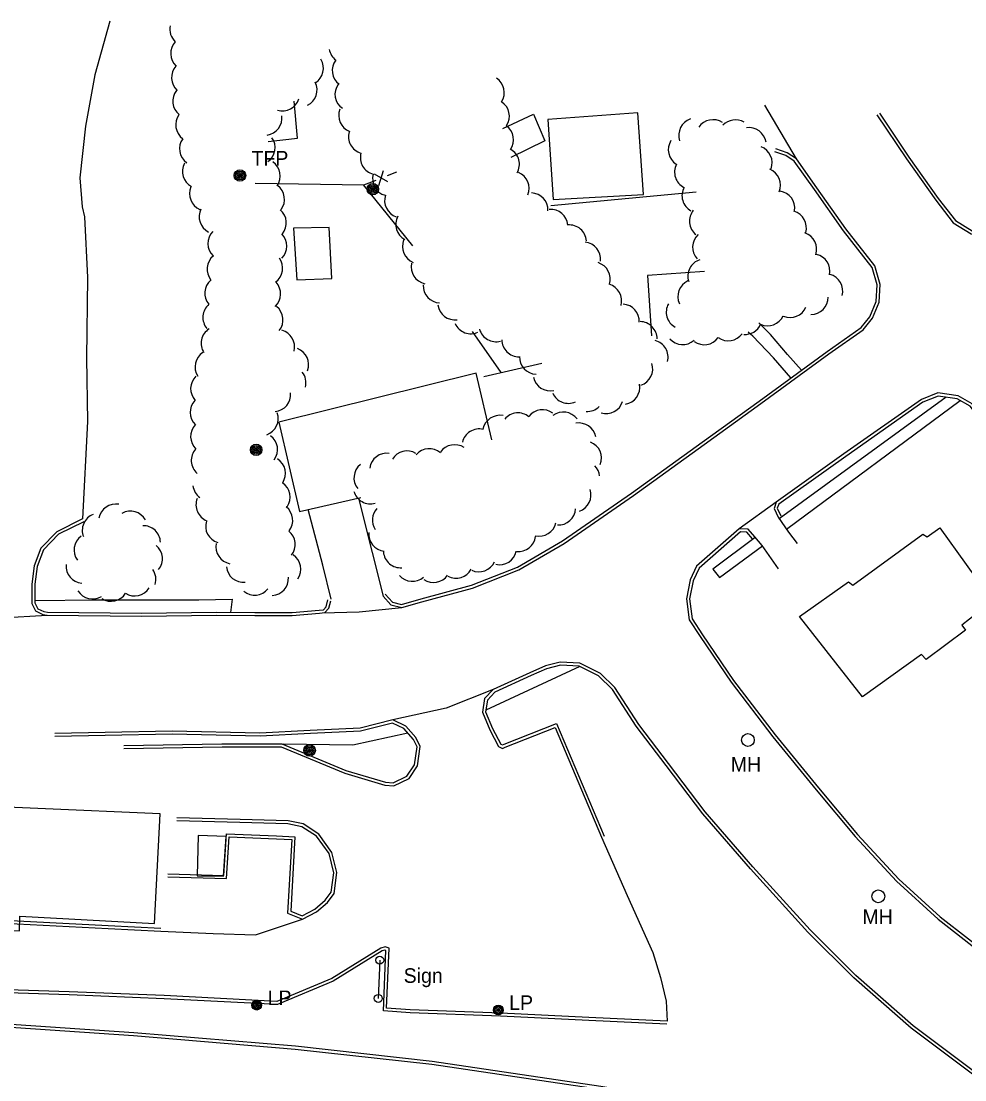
# Model space of a CAD drawing. Extents: x 2402803 to 2427059, y 6985292 to 6997652.
# Drawn here: x 2404260.6 to 2404570.8, y 6991972.5 to 6992320.4 of the extents above; entities that cross this region are included whole.
import ezdxf

# ---------------------------------------------------------------- set-up
doc = ezdxf.new("R2010")
doc.units = 0
for name, color, linetype in [('p_dtm sidewalk', 7, 'Continuous'), ('p_road - paved curb', 7, 'Continuous'), ('p_structure building', 7, 'Continuous'), ('p_structure fence', 7, 'Continuous'), ('p_structure sign', 7, 'Continuous'), ('p_utility manhole', 7, 'Continuous'), ('p_veg woods', 7, 'Continuous')]:
    doc.layers.add(name, color=color, linetype=linetype)

msp = doc.modelspace()

# ---------------------------------------------------------------- linework, layer by layer
at = {"layer": 'p_dtm sidewalk'}
for points in [[(2404517.12, 6992205.74), (2404512.51, 6992210.92), (2404506.95, 6992217.45), (2404503.04, 6992221.25)], [(2404513.62, 6992203.19), (2404507.88, 6992209.81), (2404501.12, 6992216.86), (2404499.61, 6992218.21)], [(2404564.65, 6992196.8), (2404509.76, 6992156.87)], [(2404512.15, 6992153.41), (2404569.21, 6992195.72)], [(2404501.85, 6992150.76), (2404487.91, 6992140.26), (2404490.19, 6992137.57), (2404504.25, 6992148.02)], [(2404265.16, 6992130.01), (2404284.98, 6992130.2), (2404319.04, 6992130.25), (2404329.96, 6992130.47), (2404329.39, 6992126.11)], [(2404444.25, 6992108.33), (2404413.37, 6992093.98)], [(2404387.76, 6992086.41), (2404369.65, 6992082.48), (2404346.71, 6992082.73)]]:
    msp.add_lwpolyline(points, dxfattribs=at)
at = {"layer": 'p_road - paved curb'}
for points in [[(2404289.78, 6992320.43), (2404284.83, 6992302.81), (2404281.76, 6992285.94), (2404279.93, 6992268.95), (2404280.67, 6992259.44), (2404281.41, 6992256.17), (2404282.47, 6992236.2), (2404282.13, 6992209.71), (2404282.44, 6992188.88), (2404280.76, 6992156.81)], [(2404515.43, 6992275.19), (2404505.09, 6992292.79)], [(2404541.89, 6992289.6), (2404551.55, 6992275.14), (2404561.19, 6992261.59), (2404566.97, 6992254.18), (2404572.84, 6992250.5), (2404578.63, 6992250.18), (2404584.37, 6992253.74), (2404606.98, 6992269.73), (2404617.83, 6992277.89)], [(2404542.72, 6992290.16), (2404552.37, 6992275.71), (2404561.99, 6992262.19), (2404567.65, 6992254.93), (2404573.15, 6992251.48), (2404578.37, 6992251.2), (2404583.82, 6992254.57), (2404606.39, 6992270.54), (2404617.23, 6992278.69)], [(2404379.56, 6992131.46), (2404382.08, 6992128.59), (2404385.69, 6992127.7), (2404392.32, 6992129.56), (2404408.92, 6992134.09), (2404424.16, 6992140.05), (2404439.09, 6992148.77), (2404461.82, 6992164.48), (2404485.07, 6992181.25), (2404503.75, 6992194.74), (2404526.08, 6992211.05), (2404537.39, 6992218.98), (2404540.43, 6992222.76), (2404542.62, 6992228.11), (2404542.97, 6992233.92), (2404541.16, 6992239.98), (2404531.68, 6992252.15), (2404522.16, 6992265.68), (2404515.43, 6992275.19), (2404512.36, 6992277.13), (2404508.62, 6992278.47)], [(2404380.31, 6992132.12), (2404382.62, 6992129.49), (2404385.67, 6992128.73), (2404392.05, 6992130.52), (2404408.61, 6992135.04), (2404423.72, 6992140.95), (2404438.55, 6992149.61), (2404461.24, 6992165.3), (2404484.48, 6992182.06), (2404503.16, 6992195.55), (2404525.5, 6992211.86), (2404536.7, 6992219.72), (2404539.56, 6992223.27), (2404541.63, 6992228.34), (2404541.96, 6992233.8), (2404540.26, 6992239.51), (2404530.88, 6992251.55), (2404521.34, 6992265.1), (2404514.73, 6992274.45), (2404511.92, 6992276.23), (2404508.28, 6992277.53)], [(2404652.26, 6992097.97), (2404652.95, 6992100.23), (2404651.9, 6992102.87), (2404645.97, 6992107.33), (2404634.67, 6992118.26), (2404622.7, 6992130.84), (2404611.38, 6992143.67), (2404600.52, 6992157.75), (2404592.54, 6992168.48), (2404582.61, 6992182.29), (2404573.2, 6992194.65), (2404568.54, 6992197.23), (2404561.85, 6992198.22), (2404556.52, 6992196.03), (2404531.05, 6992178.19), (2404508.81, 6992162.33), (2404508.06, 6992160.26), (2404509.4, 6992157.39)], [(2404651.3, 6992098.26), (2404651.89, 6992100.19), (2404651.07, 6992102.24), (2404645.32, 6992106.57), (2404633.96, 6992117.56), (2404621.96, 6992130.16), (2404610.61, 6992143.03), (2404599.72, 6992157.15), (2404591.73, 6992167.89), (2404581.81, 6992181.7), (2404572.53, 6992193.88), (2404568.21, 6992196.27), (2404561.98, 6992197.19), (2404557, 6992195.15), (2404531.63, 6992177.37), (2404509.64, 6992161.7), (2404509.14, 6992160.31), (2404510.31, 6992157.81)], [(2404371.52, 6992163.68), (2404375.95, 6992145.8), (2404379.56, 6992131.46)], [(2404508.81, 6992162.33), (2404496.64, 6992153.58)], [(2404362.48, 6992130.43), (2404359.77, 6992141.59), (2404354.94, 6992159.97)], [(2404509.4, 6992157.39), (2404512.76, 6992152.52), (2404515.68, 6992148.72)], [(2404280.76, 6992156.81), (2404272.31, 6992152.61), (2404267.1, 6992147.18), (2404264.91, 6992141.41), (2404264.12, 6992135.39), (2404264.17, 6992129), (2404265.4, 6992126.57), (2404267.72, 6992125.43), (2404269.17, 6992125.15), (2404300.21, 6992124.81), (2404324.88, 6992125.14), (2404337.39, 6992125.06), (2404349.71, 6992125.06), (2404358.69, 6992125.79), (2404360.45, 6992126.04), (2404361.75, 6992127.47), (2404362.43, 6992129.93)], [(2404281.21, 6992155.91), (2404272.91, 6992151.79), (2404267.96, 6992146.63), (2404265.89, 6992141.16), (2404265.12, 6992135.33), (2404265.17, 6992129.24), (2404266.14, 6992127.32), (2404268.04, 6992126.39), (2404269.27, 6992126.15), (2404300.21, 6992125.81), (2404324.88, 6992126.14), (2404337.39, 6992126.06), (2404349.67, 6992126.06), (2404358.58, 6992126.78), (2404359.95, 6992126.98), (2404360.85, 6992127.97), (2404361.47, 6992130.2)], [(2404501.7, 6992150.93), (2404499.58, 6992153.4), (2404496.64, 6992153.58), (2404482.62, 6992141.29), (2404480.49, 6992136.82), (2404479.25, 6992130.53), (2404480.15, 6992123.66), (2404483.73, 6992118.14), (2404493.97, 6992103.13), (2404507.64, 6992085.19), (2404521.88, 6992067.76), (2404534.69, 6992052.46), (2404548.35, 6992037.72), (2404562.03, 6992025.28), (2404580.65, 6992010.71), (2404597.3, 6991998.61), (2404617.12, 6991985.31), (2404648.64, 6991969.01), (2404673.8, 6991958.27), (2404698.14, 6991949.12), (2404726.05, 6991941.52), (2404750.43, 6991937.37), (2404771.59, 6991934.51), (2404778.59, 6991933.99)], [(2404500.94, 6992150.28), (2404499.1, 6992152.43), (2404496.99, 6992152.56), (2404483.43, 6992140.67), (2404481.45, 6992136.5), (2404480.26, 6992130.5), (2404481.11, 6992124.01), (2404484.56, 6992118.69), (2404494.78, 6992103.72), (2404508.43, 6992085.81), (2404522.65, 6992068.4), (2404535.44, 6992053.12), (2404549.05, 6992038.43), (2404562.68, 6992026.04), (2404581.25, 6992011.51), (2404597.87, 6991999.43), (2404617.63, 6991986.17), (2404649.07, 6991969.92), (2404674.17, 6991959.2), (2404698.45, 6991950.07), (2404726.27, 6991942.5), (2404750.58, 6991938.36), (2404771.69, 6991935.51), (2404778.66, 6991934.99)], [(2404509.56, 6992140.44), (2404504.18, 6992148.12), (2404501.7, 6992150.93)], [(2404359.57, 6992125.91), (2404371.77, 6992126.24), (2404385.69, 6992127.7)], [(2404129.3, 6992124.44), (2404174.84, 6992124.84), (2404202.49, 6992124.13), (2404239.93, 6992124.73), (2404253.96, 6992124.34), (2404269.17, 6992125.15)], [(2404573.9, 6991975.13), (2404553.78, 6991990.21), (2404534.96, 6992006.76), (2404519.93, 6992021.72), (2404501.11, 6992042.43), (2404485.4, 6992060.56), (2404473.36, 6992076.39), (2404463.6, 6992089.27), (2404455.76, 6992101.36), (2404450.99, 6992106.05), (2404444.27, 6992109.44), (2404437.75, 6992109.7), (2404433, 6992108.53), (2404427.82, 6992106.25), (2404415.72, 6992100.71), (2404412.91, 6992097.75), (2404412.26, 6992093.3), (2404414.68, 6992087.46), (2404417.53, 6992082.05), (2404418.77, 6992081.4), (2404419.74, 6992081.83), (2404436.08, 6992088.24), (2404451.31, 6992052.16)], [(2404573.33, 6991974.31), (2404553.15, 6991989.43), (2404534.28, 6992006.03), (2404519.21, 6992021.03), (2404500.36, 6992041.77), (2404484.62, 6992059.93), (2404472.56, 6992075.79), (2404462.78, 6992088.7), (2404454.98, 6992100.72), (2404450.4, 6992105.23), (2404444.01, 6992108.45), (2404437.85, 6992108.7), (2404433.32, 6992107.58), (2404428.23, 6992105.34), (2404416.31, 6992099.88), (2404413.85, 6992097.29), (2404413.29, 6992093.43), (2404415.59, 6992087.89), (2404418.27, 6992082.79), (2404418.81, 6992082.51), (2404419.35, 6992082.75), (2404436.62, 6992089.53), (2404452.23, 6992052.55)], [(2404415.72, 6992100.71), (2404400.36, 6992094.6), (2404382.75, 6992090.74)], [(2404294.35, 6992081.39), (2404326.64, 6992081.87), (2404346.11, 6992081.9), (2404366.97, 6992073.22), (2404380.14, 6992069.31), (2404383.14, 6992069.07), (2404388.11, 6992071.53), (2404390.84, 6992075.62), (2404391.81, 6992082.04), (2404390.39, 6992084.92), (2404387.05, 6992088.73), (2404382.75, 6992090.74), (2404372.02, 6992088.05), (2404355.63, 6992087.31), (2404339.11, 6992086.41), (2404310.23, 6992087.02), (2404288.24, 6992086.65), (2404271.66, 6992086.28)], [(2404294.34, 6992082.39), (2404326.63, 6992082.87), (2404346.31, 6992082.9), (2404367.31, 6992074.16), (2404380.32, 6992070.3), (2404382.94, 6992070.09), (2404387.43, 6992072.31), (2404389.88, 6992075.99), (2404390.77, 6992081.88), (2404389.55, 6992084.36), (2404386.44, 6992087.91), (2404382.65, 6992089.68), (2404372.17, 6992087.06), (2404355.68, 6992086.31), (2404339.13, 6992085.41), (2404310.23, 6992086.02), (2404288.26, 6992085.65), (2404271.68, 6992085.28)], [(2404308.79, 6992039.21), (2404328.13, 6992038.6), (2404329.04, 6992052.3), (2404344.55, 6992051.7), (2404349.54, 6992051.42), (2404348.17, 6992027.26), (2404353.05, 6992025.3), (2404357.68, 6992027.68), (2404361.3, 6992030.79), (2404363.51, 6992033.72), (2404364.43, 6992040.56), (2404362.77, 6992047.22), (2404358.41, 6992053.23), (2404353.29, 6992056.55), (2404348.39, 6992057.59), (2404332.57, 6992058.06), (2404311.78, 6992058.62)], [(2404308.82, 6992040.21), (2404327.2, 6992039.63), (2404328.11, 6992053.34), (2404344.6, 6992052.7), (2404350.6, 6992052.36), (2404349.21, 6992027.92), (2404353, 6992026.4), (2404357.12, 6992028.52), (2404360.57, 6992031.48), (2404362.55, 6992034.11), (2404363.41, 6992040.5), (2404361.85, 6992046.79), (2404357.71, 6992052.49), (2404352.9, 6992055.61), (2404348.27, 6992056.59), (2404332.54, 6992057.06), (2404311.75, 6992057.62)], [(2404451.31, 6992052.16), (2404459.82, 6992033.07), (2404468.18, 6992014.28), (2404470.74, 6992006.13), (2404472.57, 6991998.34), (2404472.91, 6991991.72)], [(2404212.23, 6992047.6), (2404211.55, 6992031.3), (2404216.85, 6992026.5), (2404250.68, 6992024.17), (2404289.19, 6992022.23), (2404306.54, 6992021.29)], [(2404213.23, 6992047.56), (2404212.57, 6992031.73), (2404217.26, 6992027.47), (2404250.74, 6992025.17), (2404289.24, 6992023.23), (2404306.59, 6992022.29)], [(2404306.54, 6992021.29), (2404323.79, 6992020.59), (2404337.68, 6992020.14), (2404353.05, 6992025.3)], [(2404472.86, 6991990.72), (2404447.15, 6991991.98), (2404418.19, 6991993.37), (2404388.47, 6991994.43), (2404379.71, 6991995.13), (2404380.5, 6992015), (2404380.19, 6992015.1), (2404379.23, 6992014.82), (2404363.21, 6992004.87), (2404344.88, 6991997.24), (2404307.61, 6991999.12), (2404276.37, 6992000.36), (2404239.49, 6992001.61)], [(2404472.91, 6991991.72), (2404447.2, 6991992.98), (2404418.23, 6991994.37), (2404388.53, 6991995.43), (2404380.75, 6991996.05), (2404381.53, 6992015.71), (2404380.21, 6992016.15), (2404378.82, 6992015.74), (2404362.75, 6992005.76), (2404344.7, 6991998.25), (2404307.66, 6992000.12), (2404276.41, 6992001.36), (2404239.53, 6992002.61)], [(2404103.33, 6992011.09), (2404106.26, 6992006.83), (2404111.58, 6992001.78), (2404118.26, 6991998.08), (2404128.47, 6991995.82), (2404130.59, 6991995.17), (2404189.8, 6991993.23), (2404247.5, 6991990.45), (2404297.53, 6991986.98), (2404350.67, 6991982.58), (2404395.62, 6991977.57), (2404450.97, 6991969.36), (2404479.18, 6991964.76), (2404478.76, 6991964.34)], [(2404104.15, 6992011.66), (2404107.02, 6992007.48), (2404112.18, 6992002.59), (2404118.62, 6991999.03), (2404128.73, 6991996.79), (2404130.76, 6991996.17), (2404189.84, 6991994.23), (2404247.56, 6991991.45), (2404297.61, 6991987.98), (2404350.77, 6991983.58), (2404395.75, 6991978.56), (2404451.12, 6991970.35), (2404479.79, 6991965.67)]]:
    msp.add_lwpolyline(points, dxfattribs=at)
at = {"layer": 'p_structure building'}
for points in [[(2404341.86, 6992280.9), (2404351.45, 6992281.92), (2404350.35, 6992294.19)], [(2404418.95, 6992285.19), (2404429.05, 6992289.85), (2404432.75, 6992281.07), (2404421.58, 6992275.67)], [(2404434.69, 6992259.86), (2404482.42, 6992264.3)], [(2404485.19, 6992238.18), (2404466.52, 6992236.81), (2404467.76, 6992217.04)], [(2404415.28, 6992182.78), (2404410.18, 6992204.68), (2404345.36, 6992188.62), (2404352.15, 6992159.27), (2404372.21, 6992163.88)]]:
    msp.add_lwpolyline(points, dxfattribs=at)
for points in [[(2404433.75, 6992288.07), (2404435.46, 6992261.81), (2404465.12, 6992263.47), (2404463.29, 6992290.34)], [(2404351.2, 6992235.46), (2404362.68, 6992235.87), (2404361.91, 6992252.58), (2404350.19, 6992252.35)], [(2404533.94, 6992135.06), (2404556.95, 6992151.83), (2404558.35, 6992150.97), (2404562.58, 6992153.93), (2404579.86, 6992129.82), (2404569.81, 6992121.95), (2404570.98, 6992120.28), (2404558.02, 6992110.61), (2404556.51, 6992112.25), (2404537.1, 6992098.37), (2404516.39, 6992124.74), (2404532.51, 6992136.15)], [(2404306.31, 6992059.86), (2404225.84, 6992063.42), (2404224.31, 6992026.65), (2404240.61, 6992025.86), (2404240.19, 6992022.05), (2404260.14, 6992021.43), (2404260.18, 6992026.21), (2404304.48, 6992023.84)], [(2404318.85, 6992052.71), (2404318.46, 6992039.52), (2404327.13, 6992039.4), (2404328.05, 6992052.39)]]:
    msp.add_lwpolyline(points, close=True, dxfattribs=at)
at = {"layer": 'p_structure fence'}
for p, q in [((2404381.16, 6992267.64), (2404376.72, 6992270.19)), ((2404378.19, 6992266.46), (2404379.69, 6992271.36)), ((2404381, 6992269.69), (2404384.13, 6992270.93)), ((2404372.98, 6992266.65), (2404389.23, 6992246.58)), ((2404418.35, 6992204.97), (2404408.91, 6992218.4)), ((2404412.67, 6992203.68), (2404431.73, 6992208))]:
    msp.add_line(p, q, dxfattribs=at)
msp.add_lwpolyline([(2404337.58, 6992267.17), (2404373.29, 6992266.65), (2404377.28, 6992268.22)], dxfattribs=at)
at = {"layer": 'p_structure sign'}
msp.add_line((2404378.48, 6992011.79), (2404377.98, 6991999.22), dxfattribs=at)
for centre in [(2404378.49, 6992011.78), (2404377.99, 6991999.21)]:
    msp.add_circle(centre, 1.3, dxfattribs=at)
at = {"layer": 'p_utility manhole'}
for centre, radius in [((2404332.55, 6992269.69), 1.9), ((2404332.55, 6992269.69), 1.44), ((2404332.55, 6992269.69), 0.973), ((2404332.55, 6992269.69), 0.539), ((2404332.55, 6992269.69), 0.192), ((2404376.21, 6992265.2), 1.9), ((2404376.21, 6992265.2), 1.44), ((2404376.21, 6992265.2), 0.973), ((2404376.21, 6992265.2), 0.539), ((2404376.21, 6992265.2), 0.192), ((2404337.86, 6992179.53), 1.9), ((2404337.86, 6992179.53), 1.44), ((2404337.86, 6992179.53), 0.973), ((2404337.86, 6992179.53), 0.539), ((2404337.86, 6992179.53), 0.192), ((2404499.48, 6992084.15), 2.1), ((2404355.42, 6992080.75), 1.9), ((2404355.42, 6992080.75), 1.44), ((2404355.42, 6992080.75), 0.973), ((2404355.42, 6992080.75), 0.539), ((2404355.42, 6992080.75), 0.192), ((2404542.33, 6992032.78), 2.1), ((2404338.06, 6991997), 1.6), ((2404338.06, 6991997), 1.3), ((2404338.06, 6991997), 1), ((2404338.06, 6991997), 0.539), ((2404338.06, 6991997), 0.192), ((2404417.46, 6991995.4), 1.6), ((2404417.46, 6991995.4), 1.3), ((2404417.46, 6991995.4), 1), ((2404417.46, 6991995.4), 0.539), ((2404417.46, 6991995.4), 0.192)]:
    msp.add_circle(centre, radius, dxfattribs=at)
at = {"layer": 'p_veg woods'}
for centre, start, end in [((2404315.14, 6992317.82), 168.5634, 227.1972), ((2404315.44, 6992309.83), 137.1972, 227.1972), ((2404367.47, 6992312.11), 189.6148, 232.6411), ((2404354.33, 6992304.94), 301.6816, 31.6816), ((2404368.53, 6992304.2), 142.6411, 232.6411), ((2404315.71, 6992301.88), 137.8897, 227.8897), ((2404352.24, 6992297.85), 296.1809, 26.1809), ((2404413.76, 6992296.99), 327.0345, 57.0345), ((2404316.1, 6992294.17), 141.9358, 231.9358), ((2404369.42, 6992296.43), 145.1113, 235.1113), ((2404346.56, 6992296.6), 252.2573, 342.2573), ((2404415.43, 6992289.18), 327.0345, 57.0345), ((2404317.07, 6992286.37), 143.9642, 233.9642), ((2404340.69, 6992288.58), 277.8659, 7.8659), ((2404370.64, 6992289.47), 159.1111, 249.1111), ((2404416.8, 6992281.44), 325.2332, 55.2332), ((2404482.39, 6992282.94), 108.677, 198.677), ((2404488, 6992282.4), 56.2661, 146.2661), ((2404495.35, 6992282.33), 59.5511, 136.4181), ((2404373.83, 6992282.51), 164.0104, 254.0104), ((2404499.85, 6992279.79), 9.0385, 99.0385), ((2404318.33, 6992278.51), 144.5449, 234.5449), ((2404338.43, 6992278.89), 304.879, 34.879), ((2404478.96, 6992278.16), 147.6449, 237.6449), ((2404501.8, 6992273.86), 339.4921, 69.4921), ((2404377.75, 6992275.62), 165.032, 255.032), ((2404418.74, 6992273.39), 329.7958, 59.7958), ((2404319.3, 6992271.05), 151.7076, 241.7076), ((2404340.12, 6992269.61), 324.7639, 54.7639), ((2404481.02, 6992270.81), 152.733, 242.733), ((2404381.78, 6992268.62), 163.854, 253.854), ((2404421.94, 6992265.45), 338.0262, 68.0262), ((2404504.55, 6992266.5), 337.8926, 67.8926), ((2404321.58, 6992263.78), 157.0949, 247.0949), ((2404341.53, 6992261.82), 324.0618, 54.0618), ((2404483.46, 6992263.1), 151.4445, 241.4445), ((2404385.72, 6992261.48), 161.3551, 251.3551), ((2404428.12, 6992258.32), 358.1019, 88.1019), ((2404509.25, 6992258.95), 351.6003, 81.6003), ((2404324.78, 6992256.15), 153.281, 243.281), ((2404342.14, 6992254.12), 320.1742, 50.1742), ((2404434.68, 6992252.92), 5.1343, 95.1343), ((2404485.91, 6992254.71), 141.1378, 231.1378), ((2404513.04, 6992252.53), 343.9262, 73.9262), ((2404389.39, 6992253.62), 151.5991, 241.5991), ((2404327.66, 6992247.37), 136.2541, 226.2541), ((2404440.78, 6992247.81), 4.5901, 94.5901), ((2404342.29, 6992246.48), 315.2944, 45.2944), ((2404391.58, 6992246.4), 158.1178, 248.1178), ((2404445.38, 6992242.22), 353.5012, 83.5012), ((2404486.96, 6992246.12), 132.2382, 222.2382), ((2404516.4, 6992245.49), 341.1633, 71.1633), ((2404327.39, 6992238.9), 129.0037, 219.0037), ((2404340.91, 6992239.24), 305.9266, 35.9266), ((2404394.47, 6992239.66), 167.779, 257.779), ((2404448.55, 6992235.66), 342.7801, 72.7801), ((2404485.39, 6992236.63), 107.8043, 197.8043), ((2404520.77, 6992238.26), 347.7537, 77.7537), ((2404525, 6992231.73), 344.9777, 74.9777), ((2404326.62, 6992231.04), 130.4996, 220.4996), ((2404340.25, 6992230.82), 312.5649, 42.5649), ((2404398.42, 6992233.46), 177.3789, 267.3789), ((2404452.34, 6992228.52), 344.1456, 74.1456), ((2404482.1, 6992229.9), 114.4739, 204.4739), ((2404326, 6992223.04), 130.0838, 220.0838), ((2404341.04, 6992222.27), 320.9399, 50.9399), ((2404403.19, 6992227.89), 187.6141, 277.6141), ((2404458.14, 6992221.77), 356.8784, 86.8784), ((2404478.28, 6992224.79), 151.1787, 241.1787), ((2404520.15, 6992229.68), 270.2772, 0.2772), ((2404505.93, 6992225.94), 245.5396, 335.5396), ((2404513.36, 6992228.68), 246.6671, 336.6671), ((2404408.43, 6992223.32), 204.1352, 294.1352), ((2404463.97, 6992216.03), 359.4287, 89.4287), ((2404498.5, 6992223.1), 265.7314, 335.8523), ((2404325.43, 6992214.53), 122.8153, 212.8153), ((2404344.84, 6992213.41), 345.2462, 75.2462), ((2404416.7, 6992220.71), 195.313, 285.313), ((2404485.12, 6992219.72), 234.2473, 324.2473), ((2404493.02, 6992221.01), 234.2473, 324.2473), ((2404349.44, 6992207.51), 339.6922, 69.6922), ((2404424.24, 6992215.76), 180.3885, 270.3885), ((2404467.59, 6992209.99), 345.4353, 75.4353), ((2404478.05, 6992219.78), 221.435, 311.435), ((2404323.44, 6992206.79), 122.8671, 212.8671), ((2404430.05, 6992210.03), 177.829, 267.829), ((2404462.54, 6992206.16), 288.4947, 18.4947), ((2404321.97, 6992199.67), 133.4739, 223.4739), ((2404348.58, 6992201.59), 345.4881, 38.0594), ((2404434.57, 6992204.54), 191.603, 281.603), ((2404458.28, 6992200.06), 280.2609, 10.2609), ((2404321.8, 6992191.85), 136.0526, 226.0526), ((2404343.56, 6992197.72), 275.3807, 5.3807), ((2404440.47, 6992200.46), 204.1856, 294.1856), ((2404452.91, 6992197.12), 252.6695, 342.6695), ((2404431.96, 6992187.05), 52.533, 142.533), ((2404438.82, 6992186.29), 37.125, 127.125), ((2404446.67, 6992197.8), 266.2559, 313.8113), ((2404339.47, 6992189.81), 289.3564, 19.3564), ((2404417.95, 6992185.22), 79.0374, 169.0374), ((2404423.89, 6992186.02), 50.2461, 140.2461), ((2404443.96, 6992182.71), 10.8899, 100.8899), ((2404321.97, 6992183.88), 136.4973, 226.4973), ((2404411.12, 6992180.74), 76.6297, 166.6297), ((2404339.25, 6992179.61), 323.6862, 53.6862), ((2404445.69, 6992176.81), 338.6489, 68.6489), ((2404322.18, 6992176.03), 138.6613, 228.6613), ((2404380.77, 6992172.74), 81.7077, 171.7077), ((2404387.47, 6992173.51), 59.0581, 149.0581), ((2404394.77, 6992174.26), 49.6512, 139.6512), ((2404403.11, 6992175.57), 56.0642, 146.0642), ((2404341.84, 6992171.76), 327.3812, 57.3812), ((2404375.64, 6992170.3), 128.7171, 218.7171), ((2404445.09, 6992170.4), 5.9207, 43.7382), ((2404322.7, 6992168.39), 187.1473, 233.6158), ((2404343.35, 6992164.04), 325.4891, 55.4891), ((2404375.41, 6992167.43), 195.9166, 285.9166), ((2404442.25, 6992164.69), 289.0116, 19.0116), ((2404291.78, 6992156.06), 80.1469, 170.1469), ((2404323.74, 6992161.46), 158.3178, 248.3178), ((2404344.25, 6992156.34), 321.9797, 51.9797), ((2404286.36, 6992153.05), 111.2988, 201.2988), ((2404296.56, 6992153.72), 29.5787, 119.5787), ((2404381.73, 6992156.48), 137.696, 213.3306), ((2404437.21, 6992160.47), 266.6789, 356.6789), ((2404300.77, 6992148.95), 1.9744, 91.9744), ((2404326.9, 6992154.45), 162.7636, 252.7636), ((2404430.86, 6992156.78), 256.8856, 346.8856), ((2404283.68, 6992146.6), 126.1102, 216.1102), ((2404345.07, 6992148.42), 321.6007, 51.6007), ((2404380.47, 6992151.89), 174.8847, 264.8847), ((2404424.09, 6992151.74), 263.2967, 353.2967), ((2404301.42, 6992143.71), 321.0067, 51.0067), ((2404330.3, 6992147.64), 168.4327, 258.4327), ((2404346.87, 6992140.34), 325.6002, 55.6002), ((2404385.32, 6992146.41), 184.6555, 274.6555), ((2404417.85, 6992147.42), 257.5382, 347.5382), ((2404281.03, 6992141.32), 174.9092, 264.9092), ((2404299.28, 6992136.92), 342.6611, 35.7585), ((2404333.73, 6992141.62), 185.4132, 275.4132), ((2404403.61, 6992142.99), 241.1789, 331.1789), ((2404411.03, 6992145.08), 245.5265, 335.5265), ((2404342.83, 6992137.31), 273.391, 3.391), ((2404389.21, 6992141.94), 220.6793, 310.6793), ((2404396.15, 6992141.59), 235.3789, 325.3789), ((2404284.12, 6992136.15), 211.5843, 301.5843), ((2404297.95, 6992137.16), 237.7983, 327.7983), ((2404337.38, 6992137.41), 230.6996, 320.6996), ((2404290.15, 6992135.39), 237.7983, 327.7983)]:
    msp.add_arc(centre, 5.65, start, end, dxfattribs=at)

# ---------------------------------------------------------------- texts
at = {"layer": 'p_structure sign'}
msp.add_text('Sign', height=4.8, dxfattribs=at).set_placement((2404386.34, 6992004.32))
at = {"layer": 'p_utility manhole'}
for s, p in [('  TFP', (2404332.76, 6992272.97)), ('  MH', (2404490.27, 6992073.72)), ('  MH', (2404533.53, 6992023.67)), ('  LP', (2404338.06, 6991997)), ('  LP', (2404417.46, 6991995.4))]:
    msp.add_text(s, height=4.8, dxfattribs=at).set_placement(p)

doc.saveas('drawing.dxf')
